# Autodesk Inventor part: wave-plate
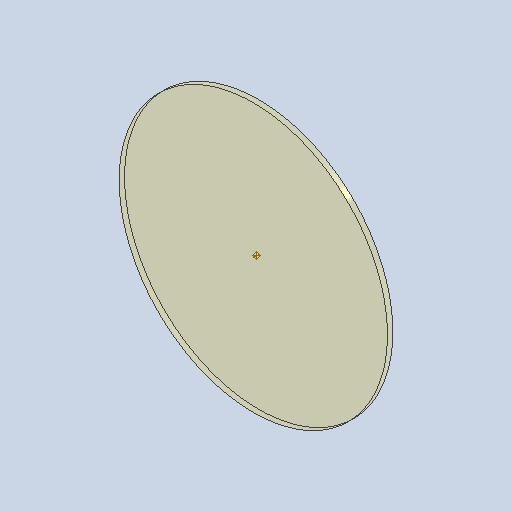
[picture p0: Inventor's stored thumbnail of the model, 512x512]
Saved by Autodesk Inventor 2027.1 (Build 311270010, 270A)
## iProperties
Created: 2026-08
Part Number: wave-plate
Material: Generic
Document SubType Name: Modeling
Designer: dunge
Density: 1 g/cm^3
Appearance: Default
Author: dunge
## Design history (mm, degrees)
sketch "Sketch1"
  geometry: C1 r 15.875 at (0, 0); 1 further point
  constraints: 1 centre point, 1 coincident
  dimensions: "d0" = 31.75 diameter of C1
extrude "Extrusion1" new body sketch "Sketch1" stored distance "d1" = 0.635; taper "d2" = 0 deg
body "Solid1"
node "Finishes"
node "Finish1" dims "Finish1_Area" = 164.67993
